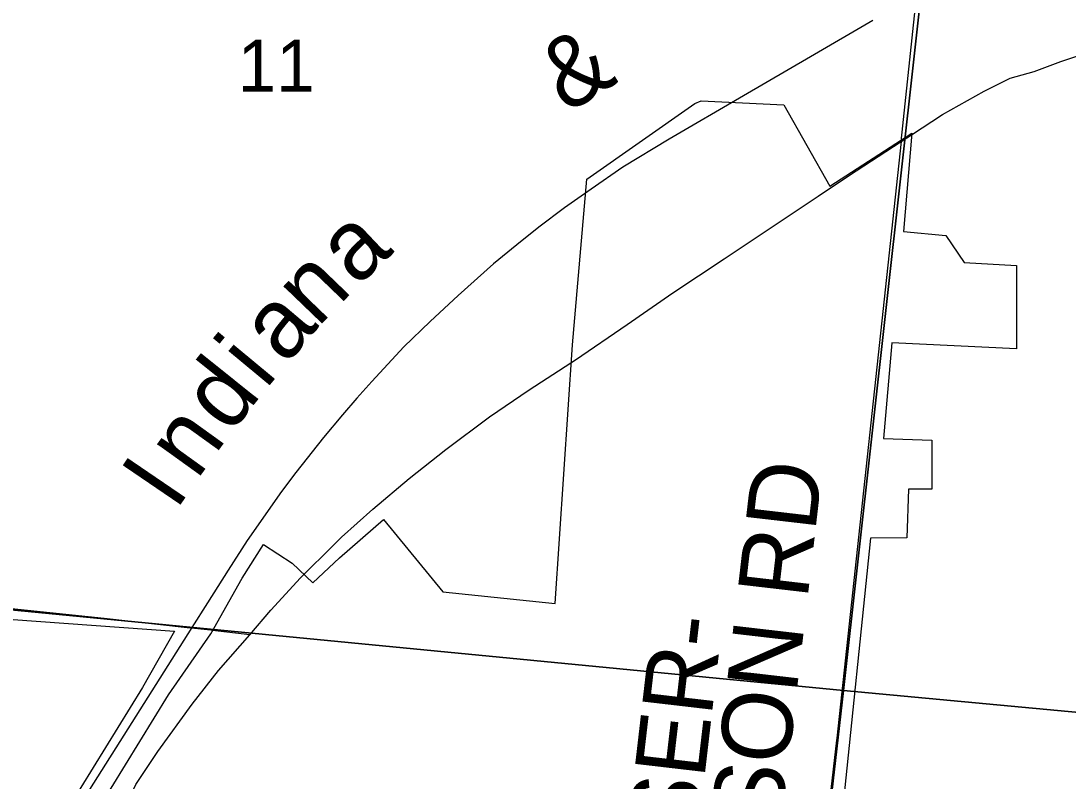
# Model space of a CAD drawing. Extents: x 0 to 34, y -4 to 22.
# Drawn here: x 4.682 to 5.277, y 20.142 to 20.574 of the extents above; entities that cross this region are included whole.
import ezdxf

# ---------------------------------------------------------------- set-up
doc = ezdxf.new("R2010")
doc.units = 0
for name, color, linetype in [('GM_X_City_Street', 7, 'Continuous'), ('GM_X_Corporation', 7, 'Continuous'), ('GM_X_Rail_Line', 7, 'Continuous'), ('GM_X_Rail_Line_Text', 7, 'Continuous'), ('GM_X_Section', 7, 'Continuous'), ('GM_X_Section_Text', 7, 'Continuous'), ('GM_X_Township_Road', 7, 'Continuous'), ('GM_X_Township_Road_Text', 7, 'Continuous'), ('GM_X_US_Route', 7, 'Continuous')]:
    doc.layers.add(name, color=color, linetype=linetype)

msp = doc.modelspace()

# ---------------------------------------------------------------- linework, layer by layer
at = {"layer": 'GM_X_City_Street'}
for points in [[(5.18241, 20.50553), (5.21881, 20.84856)], [(4.79115, 20.22763), (4.79022, 20.22774), (4.77705, 20.22909)]]:
    msp.add_lwpolyline(points, dxfattribs=at)
at = {"layer": 'GM_X_Corporation'}
for points in [[(4.71724, 20.11148), (4.76612, 20.19104), (4.79017, 20.22559), (4.80797, 20.25729), (4.82003, 20.27646), (4.83645, 20.26585), (4.84808, 20.25471), (4.86323, 20.26889), (4.88827, 20.2906), (4.92201, 20.24954), (4.98592, 20.24282), (4.99565, 20.38995), (5.00388, 20.48402), (5.06527, 20.52697), (5.06884, 20.52854), (5.11588, 20.52621), (5.14203, 20.48005), (5.1886, 20.51027), (5.18374, 20.45436), (5.20784, 20.45202), (5.21831, 20.43672), (5.24807, 20.43502), (5.24807, 20.38754), (5.17727, 20.39095), (5.17241, 20.33667), (5.19996, 20.33564), (5.19996, 20.3079), (5.18663, 20.3079), (5.1858, 20.28016), (5.16512, 20.27995), (5.14892, 20.12358)], [(4.55456, 20.24262), (4.76961, 20.22708), (4.75127, 20.19517), (4.70236, 20.11556)]]:
    msp.add_lwpolyline(points, dxfattribs=at)
at = {"layer": 'GM_X_Rail_Line'}
msp.add_lwpolyline([(5.16635, 20.57418), (5.13104, 20.55352), (5.09289, 20.53144), (5.05069, 20.50684), (5.02434, 20.49088), (5.00631, 20.47842), (4.99122, 20.46781), (4.97657, 20.45677), (4.964, 20.44682), (4.95088, 20.436), (4.93066, 20.41785), (4.91491, 20.4032), (4.89994, 20.38877), (4.88168, 20.36899), (4.87315, 20.35959), (4.86495, 20.35018), (4.85413, 20.33718), (4.83839, 20.31739), (4.8303, 20.30646), (4.81073, 20.27869), (4.80002, 20.26185), (4.78832, 20.24327), (4.77947, 20.22928), (4.68709, 20.08322)], dxfattribs=at)
at = {"layer": 'GM_X_Section'}
for points in [[(4.70982, 20.9), (4.50082, 20.9), (4.43591, 20.26255), (5.14968, 20.19347), (5.22276, 20.85012)], [(5.90509, 20.47803), (5.93966, 20.77778), (5.22276, 20.85012), (5.14968, 20.19347), (5.54309, 20.15662), (5.54309, 20.47803)], [(5.11039, 19.84879), (5.14968, 20.19347), (4.43591, 20.26255), (4.3923, 19.84879)], [(5.83395, 19.84879), (5.85296, 20.0213), (5.54309, 20.0213), (5.54309, 20.15662), (5.14968, 20.19347), (5.11039, 19.84879)]]:
    msp.add_lwpolyline(points, close=True, dxfattribs=at)
at = {"layer": 'GM_X_Township_Road'}
for points in [[(5.18241, 20.50553), (5.14589, 20.16632)], [(4.77705, 20.22909), (4.77665, 20.22913), (4.7296, 20.23438), (4.67689, 20.23986), (4.6358, 20.24216), (4.55863, 20.24914), (4.5402, 20.25032), (4.53199, 20.25424), (4.52769, 20.25592), (4.524, 20.25651), (4.51906, 20.25579), (4.50668, 20.25546), (4.49338, 20.25599), (4.48879, 20.25649)], [(4.81227, 20.22515), (4.79115, 20.22763)], [(5.14589, 20.16632), (5.14576, 20.16514), (5.10935, 19.84879)]]:
    msp.add_lwpolyline(points, dxfattribs=at)
at = {"layer": 'GM_X_US_Route'}
for points in [[(5.1883, 20.50934), (5.20593, 20.52075), (5.22972, 20.53403), (5.24438, 20.5415), (5.25818, 20.54531), (5.27331, 20.55085), (5.29679, 20.5586), (5.31943, 20.56503), (5.34803, 20.57374), (5.37715, 20.58216), (5.40627, 20.59084), (5.41064, 20.59222)], [(5.13528, 20.47439), (5.15253, 20.48589), (5.18241, 20.50553), (5.1883, 20.50934)], [(4.99477, 20.37964), (4.99737, 20.38133), (5.02679, 20.40151), (5.0528, 20.41936), (5.08185, 20.43872), (5.11311, 20.45961), (5.13528, 20.47439)], [(4.84547, 20.26175), (4.85584, 20.27199), (4.86449, 20.28052), (4.8822, 20.29645), (4.90288, 20.3139), (4.92382, 20.33049), (4.94858, 20.34906), (4.97116, 20.36427), (4.99477, 20.37964)], [(4.55567, 19.84879), (4.56024, 19.85719), (4.56964, 19.87007), (4.58508, 19.8887), (4.60437, 19.91206), (4.62393, 19.93541), (4.64404, 19.95928), (4.65864, 19.97633), (4.66535, 19.98848), (4.67373, 20.00326), (4.68469, 20.02521), (4.69839, 20.05003), (4.71492, 20.08121), (4.72502, 20.1005), (4.7378, 20.12053), (4.74762, 20.14003), (4.75999, 20.15873), (4.77948, 20.1856), (4.7945, 20.20483), (4.81227, 20.22515), (4.82426, 20.23906), (4.84112, 20.25744), (4.84547, 20.26175)]]:
    msp.add_lwpolyline(points, dxfattribs=at)

# ---------------------------------------------------------------- texts
at = {"layer": 'GM_X_Rail_Line_Text'}
for s, rotation, p in [('&', 31.86214, (4.99243, 20.52099)), ('a', 43.40377, (4.87317, 20.42254)), ('n', 46.07915, (4.85085, 20.39934)), ('a', 49.74268, (4.83288, 20.37807)), ('i', 50.3172, (4.82136, 20.36418)), ('d', 51.30788, (4.80097, 20.33873)), ('n', 54.25497, (4.78222, 20.31264)), ('I', 55.74307, (4.77021, 20.295))]:
    msp.add_text(s, height=0.03975, rotation=rotation, dxfattribs=at).set_placement(p)
at = {"layer": 'GM_X_Section_Text'}
msp.add_text('11', height=0.029444, rotation=0.00001, dxfattribs=at).set_placement((4.80542, 20.53387))
at = {"layer": 'GM_X_Township_Road_Text'}
for s, rotation, p in [('RICHARDSON RD', 83.38905, (5.08608, 19.87278)), ('GLOSSER-', 83.35729, (5.04926, 19.95967))]:
    msp.add_text(s, height=0.04, rotation=rotation, dxfattribs=at).set_placement(p)

doc.saveas('drawing.dxf')
